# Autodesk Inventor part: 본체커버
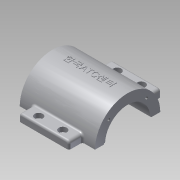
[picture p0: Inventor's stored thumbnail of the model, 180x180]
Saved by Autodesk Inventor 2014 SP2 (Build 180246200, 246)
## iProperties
Created: 2015-12
Part Number: 본체커버
Material: 알루미늄 6061
Document SubType Name: Modeling
Designer: mduedu
Density: 2.71 g/cm^3
Mass: 199.348 g
Surface Area: 200.806 cm^2
Volume: 73.5601 cm^3
Appearance: 알루미늄 - 평지
Author: mduedu
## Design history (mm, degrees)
sketch "스케치1"
  geometry: L1 (45, 40)-(-45, 40); L2 (-45, 40)-(-45, -40); L3 (-45, -40)-(45, -40); L4 (45, -40)-(45, 40); L5 (45, 40)-(-45, -40); L6 (-45, 40)-(45, -40); 1 further point
  constraints: 12 end point, 2 midpoint, 2 parallel, 1 horizontal, 1 perpendicular
  dimensions: "d0" = 90 distance of L2.end L3.end; "d2" = 80 distance of L1.end L2.end
extrude "돌출1" new body sketch "스케치1" distance "d3" = 10; taper "d4" = 0 deg
sketch "스케치2"
  geometry: L1 (0, 40)-(0, -40) reference; C1 r 32.5 at (80, 0); 1 further point
  constraints: 1 centre point
  dimensions: "d5" = 65 diameter of C1; "d6" = 80 distance from line of C1.centre L1
extrude "돌출2" join sketch "스케치2" stored distance "d7" = 75; taper "d8" = 0 deg
sketch "스케치3"
  geometry: L1 (-27.5, -20)-(27.5, -20); L2 (27.5, -20)-(27.5, 20); L3 (27.5, 20)-(-27.5, 20); L4 (-27.5, 20)-(-27.5, -20); L5 (-27.5, -20)-(27.5, 20); L6 (27.5, -20)-(-27.5, 20); 1 further point
  constraints: 12 end point, 2 midpoint, 2 parallel, 1 horizontal, 1 perpendicular
  dimensions: "d9" = 55 distance of L2.end L3.end; "d11" = 40 distance of L1.end L2.end
extrude "돌출3" new body sketch "스케치3" stored distance "d12" = 75; taper "d13" = 0 deg
fillet "모깎기1"
fillet "모깎기2"
feature "결합1"
  node "솔리드2"
fillet "모깎기3" dims "d14" = 10
sketch "스케치4"
  geometry: L1 (-37.5, 47.5)-(37.5, 47.5) reference; L2 (35, 10)-(45, 10) reference; L3 (32.5, 47.5)-(40, 10); L4 (37.5, 47.5)-(37.5, 112.5) reference; L5 (45, 10)-(45, 0) reference; 1 further point
  constraints: 2 end point, 1 midpoint, 1 point on line
  dimensions: "d15" = 5 distance from line of L3.start L4; "d16" = 5 distance from line of L3.end L5
sketch "스케치5"
  geometry: L1 (10, 40)-(10, 30) reference; L2 (10, 35)-(56.569, 22.522); L3 (0, 40)-(10, 40) reference; 2 further points
  constraints: 2 end point, 1 midpoint, 2 other
  dimensions: "d17" = 5 distance from line of L2.start L3; "d18" = 15 deg angle of L2 L3
feature "리브1" dims "d19" = 1, "d20" = 6, "d21" = 0, "d22" = 0, "d23" = 1, "d24" = 1
feature "리브2" dims "d25" = 1, "d26" = 6, "d27" = 0, "d28" = 0, "d29" = 1, "d30" = 1
fillet "모깎기4" dims "d31" = 2
fillet "모깎기5" dims "d32" = 2
fillet "모깎기6" dims "d33" = 2
sketch "스케치6"
  geometry: A1 r 10 centre (-35, 30) between (-35, 40) and (-45, 30) reference; A2 r 10 centre (35, 30) between (45, 30) and (35, 40) reference; A3 r 10 centre (35, -30) between (35, -40) and (45, -30) reference; A4 r 10 centre (-35, -30) between (-45, -30) and (-35, -40) reference; 5 further points
  constraints: 4 coincident
hole "구멍1" sketch "스케치6" at (-35, 30), (35, 30), (35, -30), (-35, -30) diameter "d34" = 7; stored, may be unused: countersink angle "d38" = 90 deg, drill point angle "d40" = 118 deg; dims "d35" = 6, "d36" = 12, "d37" = 3, "d39" = 8
fillet "모깎기7" dims "d41" = 2
hole "구멍2" diameter "d44" = 45; stored, may be unused: countersink angle "d48" = 90 deg, drill point angle "d50" = 118 deg; dims "d42" = 10, "d43" = 10, "d45" = 6, "d46" = 4, "d47" = 2, "d49" = 8
sketch "스케치7" dims "d52" = 26.5
  geometry: L1 (0, 0)-(32.5, 0); L2 (0, 0)-(22.981, 22.981); A1 r 32.5 centre (0, 0) between (32.5, 0) and (22.981, 22.981) reference; 3 further points
  constraints: 4 end point, 2 point on circle, 1 coincident, 1 horizontal, 1 point on line, 3 other
  dimensions: "d51" = 45 deg angle of L2 L1
hole "구멍3" sketch "스케치7" at (18.738, 18.738) diameter "d54" = 2.459; stored, may be unused: countersink angle "d58" = 90 deg, drill point angle "d60" = 118 deg; dims "d55" = 8, "d56" = 4, "d57" = 2, "d59" = 10
sketch "스케치8"
  geometry: L1 (72.5, 31.623)-(72.5, 46); L2 (72.5, 46)-(87.5, 46); L3 (87.5, 46)-(87.5, 31.623); A1 r 32.5 centre (80, 0) between (87.5, 31.623) and (72.5, 31.623) reference; 2 further points
  constraints: 6 end point, 2 point on circle, 1 midpoint, 1 parallel, 1 vertical, 1 vertical alignment
  dimensions: "d64" = 15 distance of L1.end L2.end; "d66" = 46 distance from line of L2 A1.centre
extrude "돌출4" join sketch "스케치8" stored distance "d67" = 50; taper "d68" = 0 deg
fillet "모깎기8" dims "d69" = 3
fillet "모깎기9" dims "d70" = 2
sketch "스케치13"
  geometry: L1 (-46, 80)-(106, 80); L2 (106, 80)-(106, -30); L3 (106, -30)-(-46, -30); L4 (-46, -30)-(-46, 80); L5 (0, 0)-(60, 0) reference; L6 (76, 75.5)-(76, 84.5) reference; C1 r 32.5 at (30, 80) reference; 1 further point
  constraints: 8 end point, 2 parallel, 1 coincident, 1 horizontal, 1 midpoint, 1 perpendicular
  dimensions: "d99" = 30 distance between parallel lines of L3 L5; "d100" = 30 distance between parallel lines of L2 L6
extrude "돌출8" cut sketch "스케치13" stored distance "d97" = 10; taper "d98" = 0 deg
node "작업 평면2"
sketch "스케치14"
  geometry: 2 further points
  constraints: 1 coincident, 1 other
feature "엠보싱1" sketch "스케치14" dims "d28" = 0, "d102" = 0.5, "d103" = 0
feature "립1" dims "d104" = 1, "d105" = 1.1, "d106" = 0, "d107" = 0, "d108" = 3 deg, "d109" = 0
sketch "스케치15"
  geometry: L1 (-3, -1.039)-(-3, -10.834) reference; L2 (47, -10.834)-(47, -1.039) reference; L3 (-3, -5.936)-(47, -5.936); L4 (-15.5, 65.666)-(-15.5, 0.666) reference; L5 (59.5, 0.666)-(59.5, 65.666) reference; L6 (-15.5, 33.166)-(59.5, 33.166); 5 further points
  constraints: 4 end point, 4 midpoint, 2 point on line, 2 symmetric about line
  dimensions: "d110" = 13 distance from line of point (10, -5.936) L1; "d111" = 13 distance from line of point (34, -5.936) L2
sketch "스케치16"
  geometry: 4 further points
hole "구멍5" sketch "스케치16" at (34, -5.936), (10, 72.269), (34, 72.269), (10, -5.936) diameter "d112" = 4.5; stored, may be unused: countersink angle "d116" = 90 deg, drill point angle "d118" = 0 deg; dims "d113" = 6, "d114" = 8, "d115" = 4.6, "d117" = 8
node "솔리드1"
mirror "대칭1"
mirror "대칭2"
pattern_circular "원형 패턴1" dims angle "d62" = 360 deg
mirror "대칭3"
mirror "대칭4"
